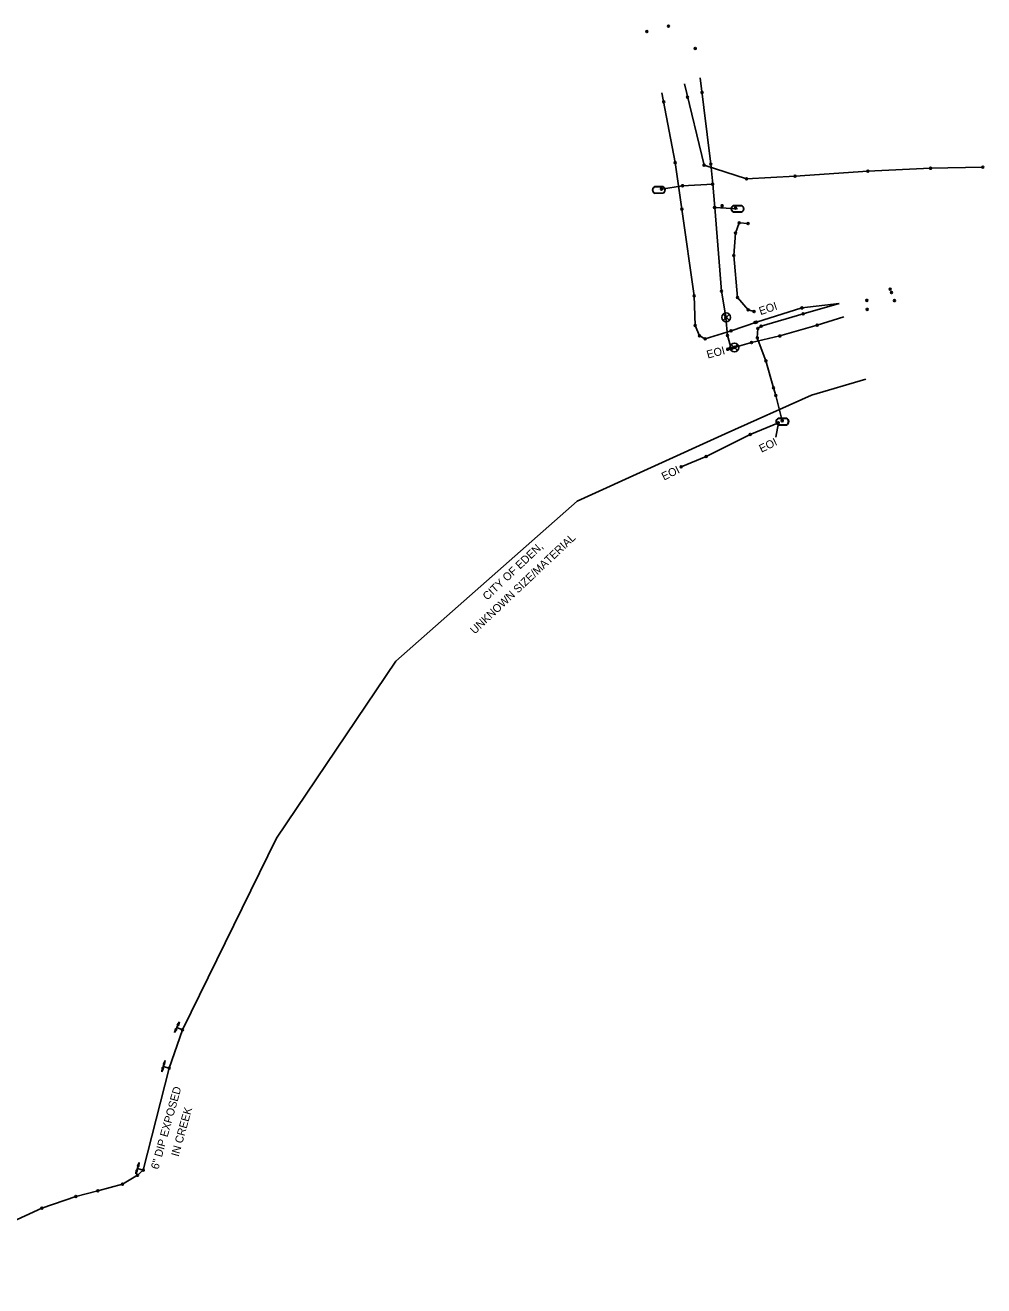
# Model space of a CAD drawing. Extents: x 1768541 to 1769517, y 999890 to 1000769.
# Drawn here: x 1769035 to 1769517, y 1000136 to 1000769 of the extents above; entities that cross this region are included whole.
import ezdxf

# ---------------------------------------------------------------- set-up
doc = ezdxf.new("R2010")
doc.units = 0
for name, color, linetype in [('Default', 7, 'Continuous'), ('Exist Utilities Other Text', 7, 'Continuous'), ('Exist Utilities Other Traffic Signal Box Leader', 7, 'Continuous'), ('Exist Utilities Other Unknown UG SUE LOS B', 7, 'Continuous'), ('Exist Utilities Telephone UG Cable SUE LOS C', 7, 'Continuous'), ('Exist Utilities Telephone UG Cable SUE LOS C Text', 7, 'Continuous'), ('Exist Utilities Water Change of Service SUE CELL', 7, 'Continuous'), ('Exist Utilities Water Meter CELL', 7, 'Continuous'), ('Exist Utilities Water Text', 7, 'Continuous'), ('Exist Utilities Water UG Line SUE LOS B', 7, 'Continuous'), ('Exist Utilities Water UG Line SUE LOS C', 7, 'Continuous'), ('Exist Utilities Water Valve CELL', 7, 'Continuous')]:
    doc.layers.add(name, color=color, linetype=linetype)

# ---------------------------------------------------------------- blocks, each defined once
blk = doc.blocks.new('SurveyPointCell')
at = {"layer": 'Default'}
for p, q in [((-0.5, 0), (0.5, 0)), ((0, -0.5), (0, 0.5))]:
    blk.add_line(p, q, dxfattribs=at)
blk.add_circle((0, 0), 0.5, dxfattribs=at)

msp = doc.modelspace()

# ---------------------------------------------------------------- linework, layer by layer
at = {"layer": 'Exist Utilities Other Traffic Signal Box Leader'}
msp.add_line((1769413.49, 1000569.2), (1769412.18, 1000562.03), dxfattribs=at)
at = {"layer": 'Exist Utilities Other Unknown UG SUE LOS B'}
for points in [[(1769366.29, 1000739.41), (1769376.16, 1000698.59), (1769397.56, 1000691.77), (1769421.87, 1000693.03), (1769458.42, 1000695.53), (1769489.96, 1000697.02), (1769516.17, 1000697.65)], [(1769355.06, 1000735), (1769361.64, 1000699.87), (1769365.1, 1000676.48), (1769371.23, 1000632.96), (1769371.76, 1000618.07), (1769373.9, 1000612.92), (1769376.75, 1000611.42), (1769389.73, 1000615.43), (1769402.46, 1000619.72)], [(1769402.46, 1000619.72), (1769425.37, 1000626.87), (1769444.07, 1000629.07)], [(1769413.49, 1000569.2), (1769399.39, 1000563.33), (1769377.24, 1000552.26), (1769364.63, 1000547.01)]]:
    msp.add_lwpolyline(points, dxfattribs=at)
at = {"layer": 'Exist Utilities Telephone UG Cable SUE LOS C'}
msp.add_lwpolyline([(1769398.27, 1000669.25), (1769393.84, 1000669.6), (1769392.02, 1000664.51), (1769391.09, 1000653.17), (1769392.99, 1000632.18), (1769398.38, 1000625.9), (1769401.28, 1000625.07)], dxfattribs=at)
at = {"layer": 'Exist Utilities Water Change of Service SUE CELL'}
for p, q in [((1769112.67, 1000268.36), (1769110.25, 1000262.92)), ((1769111.4, 1000265.5), (1769112.67, 1000268.36)), ((1769114.21, 1000264.25), (1769111.4, 1000265.5)), ((1769114.21, 1000264.25), (1769114.21, 1000264.25)), ((1769105.46, 1000248.94), (1769103.81, 1000243.22)), ((1769104.59, 1000245.93), (1769105.46, 1000248.94)), ((1769107.55, 1000245.07), (1769104.59, 1000245.93)), ((1769107.55, 1000245.07), (1769107.55, 1000245.07)), ((1769092.45, 1000197.6), (1769090.8, 1000191.87)), ((1769091.58, 1000194.59), (1769092.45, 1000197.6)), ((1769094.55, 1000193.73), (1769091.58, 1000194.59)), ((1769094.55, 1000193.73), (1769094.55, 1000193.73))]:
    msp.add_line(p, q, dxfattribs=at)
for points in [[(1769110.25, 1000262.92), (1769110.73, 1000264.86), (1769110.88, 1000264.33), (1769111.31, 1000264.56)], [(1769112.67, 1000268.36), (1769112.18, 1000266.42), (1769112.04, 1000266.95), (1769111.6, 1000266.72)], [(1769105.46, 1000248.94), (1769105.24, 1000246.95), (1769105.03, 1000247.45), (1769104.63, 1000247.17)], [(1769103.81, 1000243.22), (1769104.02, 1000245.2), (1769104.24, 1000244.71), (1769104.64, 1000244.99)], [(1769092.45, 1000197.6), (1769092.24, 1000195.61), (1769092.02, 1000196.11), (1769091.62, 1000195.83)], [(1769090.8, 1000191.87), (1769091.02, 1000193.86), (1769091.23, 1000193.36), (1769091.63, 1000193.64)]]:
    msp.add_lwpolyline(points, close=True, dxfattribs=at)
for centre in [(1769114.21, 1000264.25), (1769107.55, 1000245.07), (1769094.55, 1000193.73)]:
    msp.add_circle(centre, 0.517, dxfattribs=at)
at = {"layer": 'Exist Utilities Water Meter CELL'}
for p, q in [((1769353.47, 1000686.16), (1769353.47, 1000686.16)), ((1769392.99, 1000676.66), (1769392.99, 1000676.66)), ((1769415.54, 1000569.78), (1769415.54, 1000569.78))]:
    msp.add_line(p, q, dxfattribs=at)
for points in [[(1769355.51, 1000684.6), (1769351.41, 1000684.6)], [(1769355.51, 1000684.46), (1769351.41, 1000684.46)], [(1769351.44, 1000687.86), (1769355.51, 1000687.86)], [(1769351.44, 1000687.72), (1769355.51, 1000687.72)], [(1769390.96, 1000678.36), (1769395.03, 1000678.36)], [(1769390.96, 1000678.23), (1769395.03, 1000678.23)], [(1769395.03, 1000675.1), (1769390.93, 1000675.1)], [(1769395.03, 1000674.96), (1769390.93, 1000674.96)], [(1769413.5, 1000571.48), (1769417.58, 1000571.48)], [(1769413.5, 1000571.35), (1769417.58, 1000571.35)], [(1769417.58, 1000568.22), (1769413.48, 1000568.22)], [(1769417.58, 1000568.08), (1769413.48, 1000568.08)]]:
    msp.add_lwpolyline(points, dxfattribs=at)
for centre, radius, start, end in [((1769352.17, 1000686.15), 1.86, 113.17804, 245.97939), ((1769352.18, 1000686.15), 1.73, 115.30093, 243.78236), ((1769354.77, 1000686.16), 1.86, 293.64832, 66.30838), ((1769354.78, 1000686.16), 1.73, 295.12717, 64.87283), ((1769391.69, 1000676.66), 1.86, 113.17804, 245.97939), ((1769391.7, 1000676.66), 1.73, 115.30093, 243.78236), ((1769394.29, 1000676.66), 1.86, 293.64832, 66.30838), ((1769394.3, 1000676.66), 1.73, 295.12717, 64.87283), ((1769414.23, 1000569.78), 1.86, 113.17804, 245.97939), ((1769414.24, 1000569.78), 1.73, 115.30093, 243.78236), ((1769416.83, 1000569.78), 1.86, 293.64832, 66.30838), ((1769416.84, 1000569.78), 1.73, 295.12717, 64.87283)]:
    msp.add_arc(centre, radius, start, end, dxfattribs=at)
at = {"layer": 'Exist Utilities Water UG Line SUE LOS B'}
for p, q in [((1769392.99, 1000676.66), (1769381.56, 1000677.28)), ((1769114.21, 1000264.25), (1769107.55, 1000245.07))]:
    msp.add_line(p, q, dxfattribs=at)
for points in [[(1769374.26, 1000742.5), (1769379.58, 1000699.09), (1769380.51, 1000689.06), (1769381.56, 1000677.28), (1769384.92, 1000635.27), (1769387.08, 1000622.38), (1769387.14, 1000621.74), (1769387.98, 1000613.03), (1769389.76, 1000606.54)], [(1769354.77, 1000686.61), (1769365.41, 1000688.3), (1769380.52, 1000689.01)], [(1769415.49, 1000570.25), (1769412.25, 1000582.89), (1769411.09, 1000586.76), (1769407.29, 1000600.37), (1769402.94, 1000611.9), (1769403.25, 1000616.57), (1769404.86, 1000617.68), (1769426.02, 1000623.98), (1769444.07, 1000629.07)], [(1769388.06, 1000606.11), (1769389.24, 1000606.64), (1769391.06, 1000606.98), (1769391.85, 1000607.15), (1769400, 1000609.49), (1769414.23, 1000612.79), (1769433.01, 1000618.26), (1769446.38, 1000622.47)], [(1768961.04, 1000135.7), (1768969.18, 1000139.87), (1768971.35, 1000140.81), (1768973.43, 1000142.53), (1768978.1, 1000145.76), (1768979.43, 1000146.23), (1768989.82, 1000149.51), (1769000.69, 1000153.15), (1769026.85, 1000166.94), (1769043.64, 1000174.71), (1769060.72, 1000180.57), (1769071.68, 1000183.46), (1769084.16, 1000186.77), (1769091.58, 1000191.19), (1769094.55, 1000193.73)]]:
    msp.add_lwpolyline(points, dxfattribs=at)
at = {"layer": 'Exist Utilities Water UG Line SUE LOS C'}
msp.add_line((1769094.55, 1000193.73), (1769107.55, 1000245.07), dxfattribs=at)
msp.add_lwpolyline([(1769114.21, 1000264.25), (1769161.37, 1000360.53), (1769221.43, 1000449.38), (1769312.49, 1000529.76), (1769386.8, 1000563.64), (1769430.14, 1000583.15), (1769457.35, 1000591.16)], dxfattribs=at)
at = {"layer": 'Exist Utilities Water Valve CELL'}
for points in [[(1769388.88, 1000623.73), (1769385.73, 1000620.58), (1769387.3, 1000622.16), (1769388.88, 1000620.58), (1769385.73, 1000623.73)], [(1769393.01, 1000608.6), (1769389.86, 1000605.45), (1769391.44, 1000607.02), (1769393.01, 1000605.45), (1769389.86, 1000608.6)]]:
    msp.add_lwpolyline(points, dxfattribs=at)
for centre in [(1769387.3, 1000622.16), (1769391.44, 1000607.02)]:
    msp.add_circle(centre, 2.23, dxfattribs=at)

# ---------------------------------------------------------------- block references
at = {"layer": 'Default'}
for p in [(1769347.45, 1000765.69), (1769358.29, 1000768.4), (1769371.8, 1000757.25), (1769367.9, 1000732.77), (1769375.16, 1000735.14), (1769355.91, 1000730.44), (1769361.64, 1000699.87), (1769376.16, 1000698.59), (1769379.58, 1000699.09), (1769458.42, 1000695.53), (1769489.96, 1000697.02), (1769516.17, 1000697.65), (1769365.41, 1000688.3), (1769380.48, 1000689.01), (1769380.51, 1000689.06), (1769397.56, 1000691.77), (1769421.87, 1000693.03), (1769354.77, 1000686.61), (1769365.1, 1000676.48), (1769381.38, 1000677.35), (1769381.56, 1000677.28), (1769385.24, 1000678.25), (1769392.02, 1000676.99), (1769393.84, 1000669.6), (1769398.27, 1000669.25), (1769392.02, 1000664.51), (1769391.09, 1000653.17), (1769371.23, 1000632.96), (1769384.92, 1000635.27), (1769392.99, 1000632.18), (1769469.7, 1000636.3), (1769470.33, 1000634.62), (1769398.38, 1000625.9), (1769401.28, 1000625.07), (1769425.37, 1000626.87), (1769457.93, 1000630.7), (1769458.15, 1000626.18), (1769471.78, 1000630.55), (1769387.08, 1000622.38), (1769387.14, 1000621.74), (1769401.77, 1000619.61), (1769402.46, 1000619.72), (1769426.02, 1000623.98), (1769371.76, 1000618.07), (1769373.9, 1000612.92), (1769387.98, 1000613.03), (1769389.73, 1000615.43), (1769403.25, 1000616.57), (1769404.86, 1000617.68), (1769414.23, 1000612.79), (1769433.01, 1000618.26), (1769376.75, 1000611.42), (1769388.06, 1000606.11), (1769389.24, 1000606.64), (1769389.76, 1000606.54), (1769391.06, 1000606.98), (1769391.85, 1000607.15), (1769400, 1000609.49), (1769402.94, 1000611.9), (1769407.29, 1000600.37), (1769411.09, 1000586.76), (1769412.25, 1000582.89), (1769413.49, 1000569.2), (1769415.49, 1000570.25), (1769399.39, 1000563.33), (1769377.24, 1000552.26), (1769364.63, 1000547.01), (1769091.58, 1000191.19), (1769071.68, 1000183.46), (1769084.16, 1000186.77), (1769060.72, 1000180.57), (1769043.64, 1000174.71)]:
    msp.add_blockref('SurveyPointCell', p, dxfattribs=at)

# ---------------------------------------------------------------- texts
at = {"layer": 'Exist Utilities Other Text'}
for p in [(1769405, 1000554.12), (1769356.02, 1000540.15)]:
    msp.add_text('EOI', height=4.02, rotation=25.89282, dxfattribs=at).set_placement(p)
at = {"layer": 'Exist Utilities Telephone UG Cable SUE LOS C Text'}
msp.add_text('EOI', height=4.02, rotation=18.91176, dxfattribs=at).set_placement((1769404.56, 1000623.24))
at = {"layer": 'Exist Utilities Water Text'}
for s, rotation, p in [('EOI', 14.87307, (1769378.07, 1000601.43)), ('UNKNOWN SIZE/MATERIAL', 43.38979, (1769261, 1000462.8)), ('CITY OF EDEN, ', 43.38979, (1769267.27, 1000479.79)), ('6" DIP EXPOSED', 74.26547, (1769102.11, 1000193.91)), ('IN CREEK', 74.26547, (1769112.26, 1000200.32))]:
    msp.add_text(s, height=4.02, rotation=rotation, dxfattribs=at).set_placement(p)

doc.saveas('drawing.dxf')
